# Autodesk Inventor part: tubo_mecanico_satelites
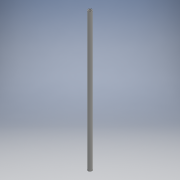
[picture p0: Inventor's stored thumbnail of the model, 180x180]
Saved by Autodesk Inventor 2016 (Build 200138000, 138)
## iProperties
Created: 2016-10
Part Number: tubo_mecanico_satelites
Material: Generic
Document SubType Name: Modeling
Designer: Ingenieria
Density: 1 g/cm^3
Appearance: Default
Author: Ingenieria
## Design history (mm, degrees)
sketch "Sketch1"
  geometry: C1 r 31.75 at (0, 0); C2 r 21.75 at (0, 0); 1 further point
  constraints: 2 centre point, 2 coincident
  dimensions: "d0" = 63.5 diameter of C1; "d1" = 43.5 diameter of C2
extrude "Extrusion1" new body sketch "Sketch1" stored distance "d2" = 2330; taper "d3" = 0 deg
body "Solid1"
